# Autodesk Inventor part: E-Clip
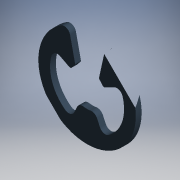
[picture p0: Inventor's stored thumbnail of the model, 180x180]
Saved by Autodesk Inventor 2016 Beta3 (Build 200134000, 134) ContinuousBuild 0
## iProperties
Shininess: 50.0
Compacted: True
Length Units: 11272
Angle Units: 11279
Time Units: 11290
Mass Units: 11286
Length Display Precision: 4
Angle Display Precision: 2
Company: Autodesk
Created: 2000-03
Part Number: E-Clip
Project: Inventor Samples
Document SubType Name: Modeling
Designer: Autodesk, Inc.
Density: 1.13 g/cm^3
Mass: 0.00688314 g
Surface Area: 0.451156 cm^2
Volume: 0.00609128 cm^3
Material: Nylon-6/6
Appearance: Dark Blue Grey
Density: 0.0
Volumn: 0.0
Area: 0.0
PropertySet Name: Model Information
Control State: 0
Master: False
Checked Out: False
Author: Autodesk, Inc.
Revision Number: A
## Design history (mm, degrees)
node "Extrusion1" dims "d2" = 0.381, "d3" = 0
  sketch "Sketch2"
    geometry: C1 r 3.175 at (-5.202, -4.223); C2 r 1.191 at (-5.202, -4.223)
    constraints: 2 centre point, 1 coincident
    dimensions: "d0" = 2.38125 diameter of C2; "d1" = 6.35 diameter of C1
node "Extrusion2" dims "d9" = 0.381, "d10" = 0
  sketch "Sketch3"
    geometry: L1 (-0.635, 0.311)-(0.635, 0.311); L2 (0.635, 0.311)-(1.27, 3.175); L3 (1.27, 3.175)-(-1.27, 3.175); L4 (-1.27, 3.175)-(-0.635, 0.311); C1 r 1.191 at (0, 0) reference; C2 r 3.175 at (0, 0) reference
    constraints: 8 end point, 1 horizontal, 1 parallel, 1 tangent
    dimensions: "d4" = 2.54 distance of L2.end L3.end; "d5" = 1.27 distance of L1.start L1.end; "d6" = 1.27 horizontal distance of C1.centre L3.end (= 0.5 x d4); "d7" = 25 deg angle of L2 L4; "d8" = 0.635 horizontal distance of C1.centre L1.start (= 0.5 x d5)
node "Extrusion3" dims "d16" = 0.381, "d17" = 0
  sketch "Sketch4"
    geometry: L1 (-3.986, -1.29)-(-4.434, -3.313) reference; L2 (-5.97, -3.313)-(-6.418, -1.29) reference; L3 (-5.705, -5.302)-(-6.222, -6.41); L4 (-4.699, -5.302)-(-4.182, -6.41); L5 (-6.281, -4.726)-(-6.281, -4.726); L6 (-5.705, -5.302)-(-5.705, -5.302); L7 (-6.258, -3.673)-(-7.342, -3.109); L8 (-4.146, -3.673)-(-3.062, -3.109); A1 r 3.175 centre (-5.202, -4.223) between (-6.418, -1.29) and (-3.986, -1.29) reference; A2 r 2.413 centre (-5.202, -4.223) between (-7.342, -3.109) and (-3.062, -3.109); 2 further points
    constraints: 12 end point, 5 point on circle, 4 point on line, 1 centre point, 1 coincident, 1 parallel, 1 vertical alignment, 10 other
    dimensions: "d11" = 50 deg angle of L4 L3; "d12" = 0.762 radial gap between concentric circles of A1 A2; "d13" = 25 deg dimension on point (-5.202, -4.223) point (-5.202, -7.398) L3.end (= 0.5 x d11); "d14" = 50 deg angle of L2 L7; "d15" = 50 deg angle of L8 L1 (= d14)
node "Fillet1" dims "d18" = 0.381, "d19" = 0.127
workaxis "Work Axis1"
body "Solid1"
